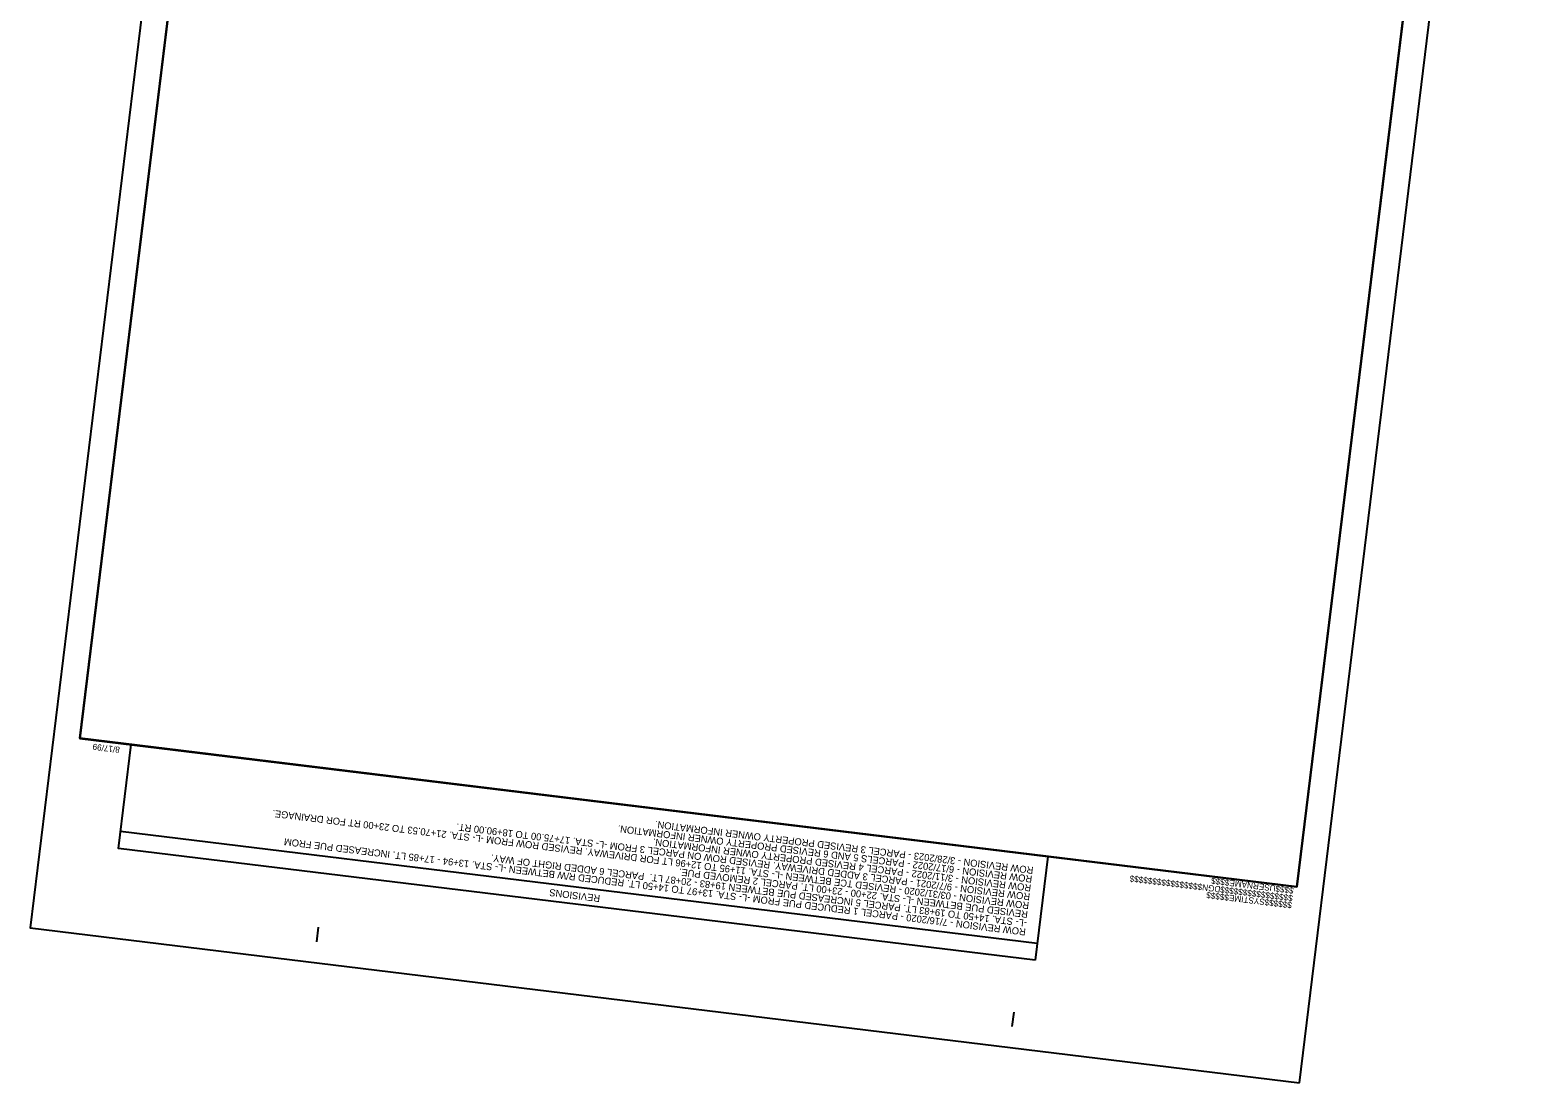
# Model space of a CAD drawing. Extents: x 480570 to 481861, y 488765 to 490569.
# Drawn here: x 480570 to 481861, y 488765 to 489667 of the extents above; entities that cross this region are included whole.
import ezdxf

# ---------------------------------------------------------------- set-up
doc = ezdxf.new("R2010")
doc.units = 0
for name, color, linetype in [('Sheet Block Revision CELL', 7, 'Continuous'), ('Sheet Clip Boundary CELL', 7, 'Continuous'), ('Sheet Plan CELL', 7, 'Continuous'), ('Sheet Plot Border Outside CELL', 7, 'Continuous')]:
    doc.layers.add(name, color=color, linetype=linetype)

msp = doc.modelspace()

# ---------------------------------------------------------------- linework, layer by layer
at = {"layer": 'Sheet Block Revision CELL'}
msp.add_line((481432.3, 488884.2), (480647.5, 488980), dxfattribs=at)
msp.add_lwpolyline([(481430.6, 488869.8), (480645.7, 488965.6), (480656.6, 489054.6), (481441.4, 488958.7)], close=True, dxfattribs=at)
at = {"layer": 'Sheet Clip Boundary CELL'}
msp.add_lwpolyline([(481654.8, 488932.5), (481816, 490252.1), (481655.1, 490245.3), (481542.7, 490356.6), (481123.7, 490407.8), (480954.5, 490428.6), (480942.4, 490329.1), (480942.4, 490329.1), (480770.1, 490350.2), (480612.5, 489059.8)], close=True, dxfattribs=at)
at = {"layer": 'Sheet Plan CELL'}
for p, q in [((480612.5, 489060), (480612.5, 489060)), ((481654.8, 488932.7), (481654.8, 488932.7)), ((480815.4, 488885.6), (480816.9, 488898)), ((481411, 488812.9), (481412.5, 488825.3))]:
    msp.add_line(p, q, dxfattribs=at)
for points in [[(480794.4, 490548.9), (480612.5, 489060), (481654.8, 488932.7), (481836.7, 490421.6)], [(481654.8, 488932.7), (480612.6, 489059.9), (480770.1, 490350.3), (480919.1, 490332.2), (480943.4, 490530.7), (481836.7, 490421.6)]]:
    msp.add_lwpolyline(points, close=True, dxfattribs=at)
at = {"layer": 'Sheet Plot Border Outside CELL'}
msp.add_lwpolyline([(481657, 488764.7), (481861.1, 490435.8), (480774.1, 490568.5), (480570, 488897.4)], close=True, dxfattribs=at)

# ---------------------------------------------------------------- texts
at = {"layer": 'Sheet Block Revision CELL'}
for s, p in [('ROW REVISION - 03/31/2020 - REVISED TCE BETWEEN -L- STA. 11+95 TO 12+96 LT FOR DRIVEWAY. REVISED ROW FROM -L- STA. 21+70.53 TO 23+00 RT FOR DRAINAGE.', (481425.7, 488919.4)), ('ROW REVISION - 3/28/2023 - PARCEL 3 REVISED PROPERTY OWNER INFORMATION.', (481429.4, 488949.6)), ('ROW REVISION - 9/7/2021 - PARCEL 3 ADDED DRIVEWAY. REVISED ROW ON PARCEL 3 FROM -L- STA. 17+75.00 TO 18+90.00 RT.', (481426.6, 488927)), ('ROW REVISION - 6/17/2022 - PARCELS 5 AND 6 REVISED PROPERTY OWNER INFORMATION.', (481428.4, 488942.1)), ('ROW REVISION - 7/16/2020 - PARCEL 1 REDUCED PUE FROM -L- STA. 13+97 TO 14+50 LT. REDUCED R/W BETWEEN -L- STA. 13+94 - 17+85 LT. INCREASED PUE FROM ', (481422.9, 488896.8)), ('ROW REVISION - 3/11/2022 - PARCEL 4 REVISED PROPERTY OWNER INFORMATION. ', (481427.5, 488934.5)), ('-L- STA. 14+50 TO 19+83 LT. PARCEL 5 INCREASED PUE BETWEEN 19+83 - 20+87 LT.  PARCEL 6 ADDED RIGHT OF WAY.', (481423.8, 488904.3)), ('REVISED PUE BETWEEN -L- STA. 22+00 - 23+00 LT. PARCEL 2 REMOVED PUE.', (481424.7, 488911.9)), ('REVISIONS', (481058.4, 488925.5))]:
    msp.add_text(s, height=6, rotation=173.0365, dxfattribs=at).set_placement(p)
at = {"layer": 'Sheet Plan CELL'}
for s, p in [('8/17/99', (480647.1, 489052.5)), ('$$$$$$$$$$$$$$$$DGN$$$$$$$$$$$$$$$$', (481651.5, 488925.4)), ('$$$$USERNAME$$$$', (481652.3, 488931.9)), ('$$$$$$SYSTIME$$$$$', (481650.8, 488919.3))]:
    msp.add_text(s, height=5.25, rotation=173.0365, dxfattribs=at).set_placement(p)

doc.saveas('drawing.dxf')
